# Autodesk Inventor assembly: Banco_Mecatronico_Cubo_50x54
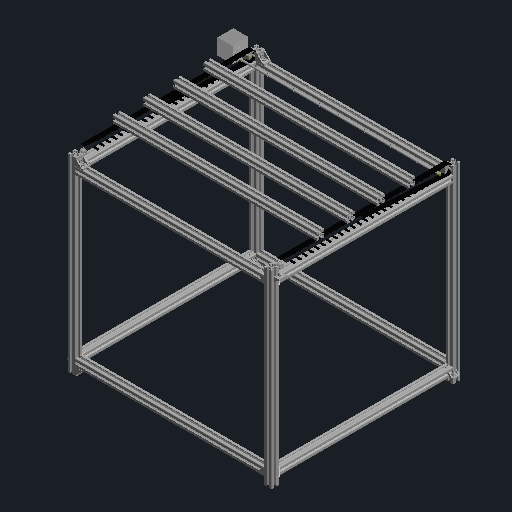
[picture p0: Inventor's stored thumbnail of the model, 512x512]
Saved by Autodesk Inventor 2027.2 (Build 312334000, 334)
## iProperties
Part Number: Banco_Mecatronico_Cubo_50x54
Document SubType Name: Ensamblaje
Designer: Usuario
Author: Usuario
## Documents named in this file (11)
- C:\Users\Usuario\Desktop\universidad\clase\TFG\DESARROLLO_TFG\Parte mecanica\Inventor\ensamblajes\Banco_Mecatronico_TFG_Principal.iam
- C:\Users\Usuario\Desktop\universidad\clase\TFG\DESARROLLO_TFG\Parte mecanica\Inventor\piezas\Perfil_2020_L500.ipt
- C:\Users\Usuario\Desktop\universidad\clase\TFG\DESARROLLO_TFG\Parte mecanica\Inventor\piezas\Perfil_2020_L460.ipt
- C:\Users\Usuario\Desktop\universidad\clase\TFG\DESARROLLO_TFG\Parte mecanica\Inventor\piezas\Escuadra_90_Fundicion_2020.ipt
- C:\Users\Usuario\Desktop\universidad\clase\TFG\DESARROLLO_TFG\Parte mecanica\Inventor\piezas\Tornillo_M5x8_DIN912.ipt
- C:\Users\Usuario\Desktop\universidad\clase\TFG\DESARROLLO_TFG\Parte mecanica\Inventor\piezas\Cinta_Transportadora_20mm_L500.ipt
- C:\Users\Usuario\Desktop\universidad\clase\TFG\DESARROLLO_TFG\Parte mecanica\Inventor\piezas\Engranaje_Recto_1a1_m1_Z20.ipt
- C:\Users\Usuario\Desktop\universidad\clase\TFG\DESARROLLO_TFG\Parte mecanica\Inventor\piezas\Motor_NEMA17.ipt
- C:\Users\Usuario\Desktop\universidad\clase\TFG\DESARROLLO_TFG\Parte mecanica\Inventor\piezas\Eje_Distribucion_5mm_L520.ipt
- C:\Users\Usuario\Desktop\universidad\clase\TFG\DESARROLLO_TFG\Parte mecanica\Inventor\piezas\Polea_GT2_20T.ipt
- C:\Users\Usuario\Desktop\universidad\clase\TFG\DESARROLLO_TFG\Parte mecanica\Inventor\piezas\Perfil_2020_L540.ipt
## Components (73 placed, 10 different names)
1. Perfil_2020_L500:1
2. Perfil_2020_L500:2
3. Perfil_2020_L500:3
4. Perfil_2020_L500:4
5. Perfil_2020_L500:5
6. Perfil_2020_L500:6
7. Perfil_2020_L460:1
8. Perfil_2020_L460:2
9. Perfil_2020_L500:7
10. Perfil_2020_L500:8
11. Perfil_2020_L460:3
12. Perfil_2020_L460:4
13. Escuadra_90_Fundicion_2020:1
14. Tornillo_M5x8_DIN912:1
15. Tornillo_M5x8_DIN912:2
16. Escuadra_90_Fundicion_2020:2
17. Tornillo_M5x8_DIN912:3
18. Tornillo_M5x8_DIN912:4
19. Escuadra_90_Fundicion_2020:3
20. Tornillo_M5x8_DIN912:5
21. Tornillo_M5x8_DIN912:6
22. Escuadra_90_Fundicion_2020:4
23. Tornillo_M5x8_DIN912:7
24. Tornillo_M5x8_DIN912:8
25. Escuadra_90_Fundicion_2020:5
26. Tornillo_M5x8_DIN912:9
27. Tornillo_M5x8_DIN912:10
28. Escuadra_90_Fundicion_2020:6
29. Tornillo_M5x8_DIN912:11
30. Tornillo_M5x8_DIN912:12
31. Escuadra_90_Fundicion_2020:7
32. Tornillo_M5x8_DIN912:13
33. Tornillo_M5x8_DIN912:14
34. Escuadra_90_Fundicion_2020:8
35. Tornillo_M5x8_DIN912:15
36. Tornillo_M5x8_DIN912:16
37. Escuadra_90_Fundicion_2020:9
38. Tornillo_M5x8_DIN912:17
39. Tornillo_M5x8_DIN912:18
40. Escuadra_90_Fundicion_2020:10
41. Tornillo_M5x8_DIN912:19
42. Tornillo_M5x8_DIN912:20
43. Escuadra_90_Fundicion_2020:11
44. Tornillo_M5x8_DIN912:21
45. Tornillo_M5x8_DIN912:22
46. Escuadra_90_Fundicion_2020:12
47. Tornillo_M5x8_DIN912:23
48. Tornillo_M5x8_DIN912:24
49. Escuadra_90_Fundicion_2020:13
50. Tornillo_M5x8_DIN912:25
51. Tornillo_M5x8_DIN912:26
52. Escuadra_90_Fundicion_2020:14
53. Tornillo_M5x8_DIN912:27
54. Tornillo_M5x8_DIN912:28
55. Escuadra_90_Fundicion_2020:15
56. Tornillo_M5x8_DIN912:29
57. Tornillo_M5x8_DIN912:30
58. Escuadra_90_Fundicion_2020:16
59. Tornillo_M5x8_DIN912:31
60. Tornillo_M5x8_DIN912:32
61. Cinta_Transportadora_20mm_L500:1
62. Cinta_Transportadora_20mm_L500:2
63. Engranaje_Recto_1a1_m1_Z20:1
64. Engranaje_Recto_1a1_m1_Z20:2
65. Motor_NEMA17:1
66. Eje_Distribucion_5mm_L520:1
67. Engranaje_Recto_1a1_m1_Z20:3
68. Polea_GT2_20T:1
69. Polea_GT2_20T:2
70. Perfil_2020_L540:1
71. Perfil_2020_L540:2
72. Perfil_2020_L540:3
73. Perfil_2020_L540:4
